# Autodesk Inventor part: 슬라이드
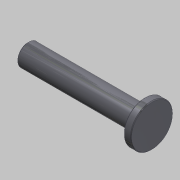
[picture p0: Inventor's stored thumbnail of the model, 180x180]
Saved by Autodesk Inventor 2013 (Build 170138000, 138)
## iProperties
Created: 2015-10
Part Number: 슬라이드
Document SubType Name: Modeling
Designer: mdu
Density: 7.86 g/cm^3
Material: 강철, 연강
Mass: 1065.95 g
Surface Area: 229.101 cm^2
Volume: 135.617 cm^3
Author: mdu
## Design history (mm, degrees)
sketch "스케치1"
  geometry: L1 (-75, 162)-(-75, 58) reference; L2 (-148, 110)-(22, 110); L3 (-148, 110)-(-148, 125); L4 (-148, 125)-(12, 125); L5 (12, 125)-(12, 139); L6 (12, 139)-(22, 139); L7 (22, 139)-(22, 110); 2 further points
  constraints: 12 end point, 3 parallel, 3 perpendicular, 1 midpoint, 1 point on line
  dimensions: "d0" = 58 diameter of L6 L2; "d1" = 30 diameter of L4 L2; "d2" = 10 distance of L5.end L6.end; "d3" = 170 distance of L2.start L2.end; "d4" = 73 distance between parallel lines of L3 L1
revolve "회전1" sketch "스케치1" stored, may be unused: angle "d5" = 90 deg
hole "구멍1" diameter "d11" = 13.376; stored, may be unused: countersink angle "d15" = 90 deg, drill point angle "d17" = 118 deg; dims "d9" = 10, "d10" = 10, "d12" = 22, "d13" = 4, "d14" = 2, "d16" = 25
chamfer "모따기1" distance "d6" = 1; stored, may be unused: second distance "d7" = 2, angle "d8" = 45 deg
node "솔리드1"
node "참조1"
